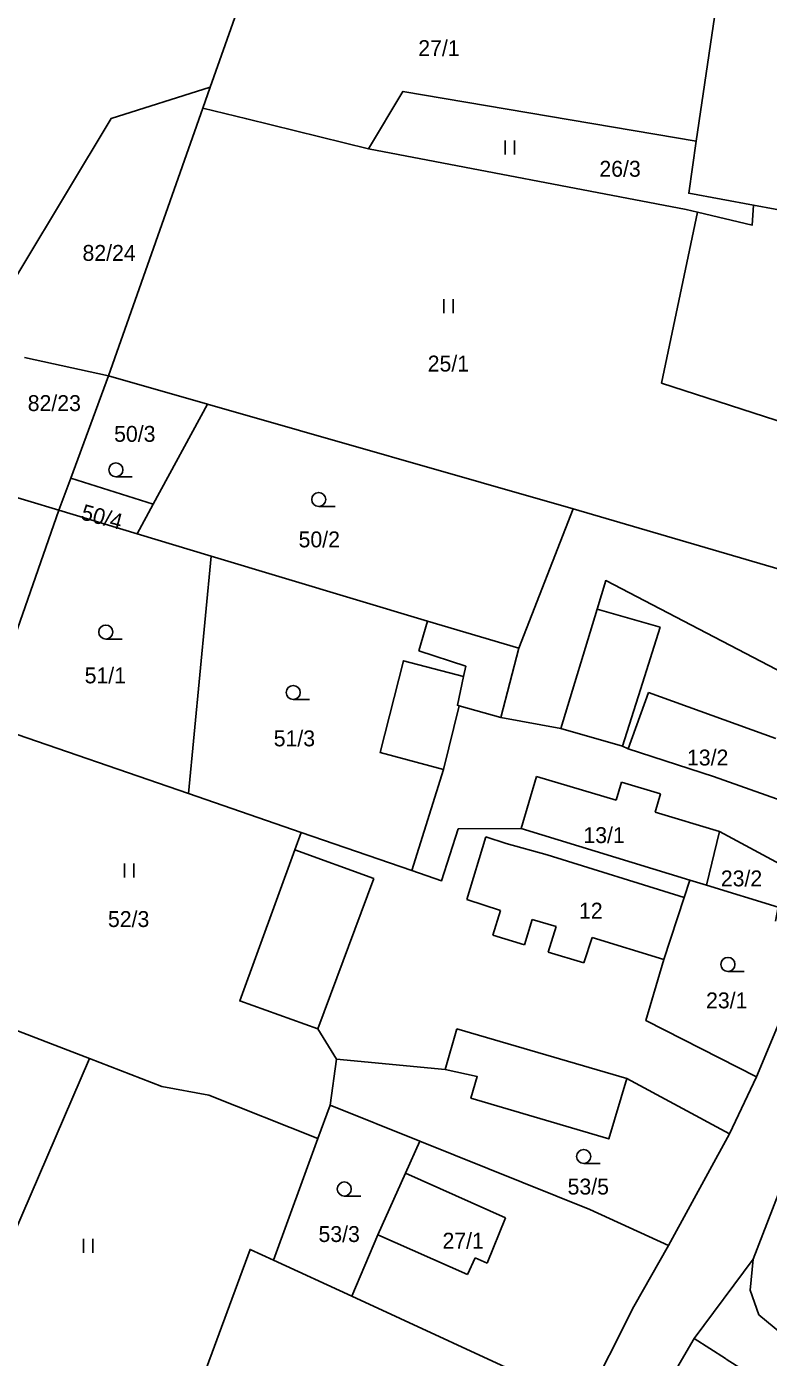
# Model space of a CAD drawing. Extents: x -746176 to -739709, y -1128407 to -1124482.
# Drawn here: x -743036.1 to -742956.8, y -1127574.6 to -1127432.2 of the extents above; entities that cross this region are included whole.
import ezdxf

# ---------------------------------------------------------------- set-up
doc = ezdxf.new("R2010")
doc.units = 0
for name, color, linetype in [('Hranice parcel', 7, 'Continuous'), ('Parcelní čísla', 7, 'Continuous'), ('Vnitřní kresba', 7, 'Continuous'), ('Značky kultur', 7, 'Continuous')]:
    doc.layers.add(name, color=color, linetype=linetype)

msp = doc.modelspace()

# ---------------------------------------------------------------- linework, layer by layer
at = {"layer": 'Hranice parcel'}
for p, q in [((-743016.5, -1127438.72), (-743010.06, -1127420.45)), ((-742962.06, -1127427.67), (-742964.54, -1127444.49)), ((-743017.29, -1127440.95), (-743016.5, -1127438.72)), ((-743017.29, -1127440.95), (-743027.39, -1127469.59)), ((-742968.23, -1127470.39), (-742964.4, -1127452.09)), ((-743027.39, -1127469.59), (-743036.38, -1127467.62)), ((-743027.39, -1127469.59), (-743031.43, -1127480.55)), ((-743027.39, -1127469.59), (-743016.81, -1127472.62)), ((-742947.25, -1127477.16), (-742968.23, -1127470.39)), ((-743016.81, -1127472.62), (-743022.6, -1127483.32)), ((-743016.81, -1127472.62), (-742977.71, -1127483.81)), ((-743031.43, -1127480.55), (-743032.69, -1127483.96)), ((-743031.43, -1127480.55), (-743022.6, -1127483.32)), ((-743032.69, -1127483.96), (-743040.81, -1127481.55)), ((-743032.69, -1127483.96), (-743040.66, -1127506.77)), ((-743024.31, -1127486.49), (-743032.69, -1127483.96)), ((-743022.6, -1127483.32), (-743024.31, -1127486.49)), ((-742977.71, -1127483.81), (-742983.49, -1127498.74)), ((-742954.21, -1127490.71), (-742977.71, -1127483.81)), ((-743024.31, -1127486.49), (-743016.42, -1127488.87)), ((-743018.83, -1127514.29), (-743016.42, -1127488.87)), ((-742983.49, -1127498.74), (-742985.43, -1127506.13)), ((-743040.66, -1127506.77), (-743018.83, -1127514.29)), ((-742979.03, -1127507.34), (-742985.43, -1127506.13)), ((-743018.83, -1127514.29), (-743006.77, -1127518.44)), ((-742983.25, -1127518.03), (-742989.99, -1127518.04)), ((-742965.23, -1127523.55), (-742983.25, -1127518.03)), ((-742994.94, -1127522.52), (-743006.77, -1127518.44)), ((-742965.23, -1127523.55), (-742963.44, -1127524.1)), ((-742958.07, -1127544.59), (-742952.01, -1127529.96)), ((-743029.41, -1127542.64), (-743050.32, -1127534.62)), ((-743029.41, -1127542.64), (-743044.5, -1127577.53)), ((-743003.69, -1127547.61), (-743002.99, -1127542.69)), ((-742960.97, -1127550.69), (-742958.07, -1127544.59)), ((-743005.01, -1127551.2), (-743003.69, -1127547.61)), ((-742994.1, -1127551.47), (-743003.69, -1127547.61)), ((-742960.97, -1127550.69), (-742967.51, -1127562.65)), ((-743009.74, -1127564.2), (-743005.01, -1127551.2)), ((-743001.38, -1127568.05), (-743009.74, -1127564.2)), ((-742964.75, -1127572.6), (-742958.43, -1127564.08)), ((-742979.47, -1127578.16), (-743001.38, -1127568.05))]:
    msp.add_line(p, q, dxfattribs=at)
for points in [[(-743041.59, -1127466.09), (-743027.12, -1127442.06), (-743016.5, -1127438.72)], [(-742964.54, -1127444.49), (-742995.91, -1127439.17), (-742999.6, -1127445.32)], [(-742999.6, -1127445.32), (-743012.61, -1127442.11), (-743017.29, -1127440.95)], [(-742964.4, -1127452.09), (-742965.61, -1127451.81), (-742999.6, -1127445.32)], [(-742964.54, -1127444.49), (-742965.34, -1127450.06), (-742958.39, -1127451.34)], [(-742958.39, -1127451.34), (-742958.54, -1127453.46), (-742964.4, -1127452.09)], [(-742958.39, -1127451.34), (-742942.2, -1127454.33), (-742938.29, -1127453.29), (-742933.5, -1127454.97), (-742931.72, -1127454.21), (-742928.29, -1127455.5)], [(-743016.42, -1127488.87), (-742993.26, -1127495.85), (-742983.49, -1127498.74)], [(-742979.03, -1127507.34), (-742975.14, -1127494.55), (-742974.21, -1127491.49), (-742943.52, -1127507.49)], [(-742985.43, -1127506.13), (-742989.89, -1127504.88), (-742990.08, -1127504.83), (-742989.41, -1127501.75), (-742995.84, -1127500.07), (-742998.35, -1127509.89), (-742991.56, -1127511.71), (-742994.94, -1127522.52)], [(-742947.48, -1127518.45), (-742949.22, -1127517.23), (-742962.69, -1127512.44), (-742971.81, -1127509.49), (-742972.41, -1127509.22), (-742979.03, -1127507.34)], [(-742989.99, -1127518.04), (-742991.77, -1127523.61), (-742994.94, -1127522.52)], [(-742963.44, -1127524.1), (-742962.06, -1127518.33), (-742949.93, -1127524.86)], [(-743006.77, -1127518.44), (-743007.45, -1127520.31), (-743013.35, -1127536.47), (-743005, -1127539.46), (-743002.99, -1127542.69)], [(-742958.07, -1127544.59), (-742969.92, -1127538.58), (-742968.01, -1127532.03), (-742965.83, -1127525.39), (-742965.23, -1127523.55)], [(-742956.04, -1127527.94), (-742955.76, -1127526.44), (-742963.44, -1127524.1)], [(-743005.01, -1127551.2), (-743016.66, -1127546.56), (-743021.68, -1127545.63), (-743029.41, -1127542.64)], [(-743002.99, -1127542.69), (-742991.4, -1127543.81), (-742987.95, -1127544.57), (-742988.63, -1127546.87), (-742973.89, -1127551.23), (-742971.94, -1127544.76), (-742960.97, -1127550.69)], [(-742958.43, -1127564.08), (-742954.72, -1127554.49), (-742950.97, -1127547.61)], [(-742994.1, -1127551.47), (-742995.64, -1127554.9), (-742998.58, -1127561.51), (-743001.38, -1127568.05)], [(-742967.51, -1127562.65), (-742975.9, -1127558.78), (-742994.1, -1127551.47)], [(-743009.74, -1127564.2), (-743012.24, -1127563.05), (-743019.38, -1127582.4), (-743017.56, -1127583.41), (-742993.08, -1127596.96), (-742990.26, -1127591.96)], [(-742967.51, -1127562.65), (-742971.19, -1127569.17), (-742976.43, -1127579.56), (-742979.47, -1127578.16)], [(-742927.53, -1127585.44), (-742934.7, -1127582.76), (-742939.64, -1127581.23), (-742943.72, -1127578.66), (-742953.72, -1127573.43), (-742957.84, -1127570.04), (-742958.76, -1127567.42), (-742958.43, -1127564.08)], [(-742964.75, -1127572.6), (-742970.21, -1127581.92), (-742973.05, -1127587.2), (-742974.2, -1127589.77)], [(-742951.01, -1127581.4), (-742957.06, -1127577.5), (-742961.32, -1127574.78), (-742961.39, -1127574.71), (-742964.75, -1127572.6)]]:
    msp.add_lwpolyline(points, dxfattribs=at)
at = {"layer": 'Vnitřní kresba'}
for p, q in [((-742975.14, -1127494.55), (-742968.39, -1127496.47)), ((-742994.2, -1127499.03), (-742993.26, -1127495.85)), ((-742970.5, -1127503.16), (-742968.39, -1127496.47)), ((-742994.2, -1127499.03), (-742989.17, -1127500.66)), ((-742989.41, -1127501.75), (-742989.17, -1127500.66)), ((-742972.41, -1127509.22), (-742970.5, -1127503.16)), ((-742971.81, -1127509.49), (-742969.62, -1127503.47)), ((-742969.62, -1127503.47), (-742956.03, -1127508.38)), ((-742991.56, -1127511.71), (-742989.89, -1127504.88)), ((-742983.25, -1127518.03), (-742981.6, -1127512.47)), ((-742981.6, -1127512.47), (-742973.1, -1127514.99)), ((-742973.1, -1127514.99), (-742972.53, -1127513.06)), ((-742972.53, -1127513.06), (-742968.35, -1127514.3)), ((-742968.94, -1127516.27), (-742968.35, -1127514.3)), ((-742968.94, -1127516.27), (-742962.06, -1127518.33)), ((-742989.07, -1127525.61), (-742987.02, -1127518.91)), ((-742987.02, -1127518.91), (-742984.85, -1127519.61)), ((-742984.85, -1127519.61), (-742980.49, -1127520.84)), ((-743007.45, -1127520.31), (-742999.03, -1127523.38)), ((-742980.49, -1127520.84), (-742965.83, -1127525.39)), ((-743005, -1127539.46), (-742999.03, -1127523.38)), ((-742989.07, -1127525.61), (-742985.46, -1127526.79)), ((-742986.28, -1127529.44), (-742985.46, -1127526.79)), ((-742982.9, -1127530.47), (-742982.08, -1127527.77)), ((-742982.08, -1127527.77), (-742979.51, -1127528.51)), ((-742986.28, -1127529.44), (-742982.9, -1127530.47)), ((-742980.35, -1127531.26), (-742979.51, -1127528.51)), ((-742976.56, -1127532.4), (-742975.66, -1127529.7)), ((-742975.66, -1127529.7), (-742968.01, -1127532.03)), ((-742980.35, -1127531.26), (-742976.56, -1127532.4)), ((-742991.4, -1127543.81), (-742990.15, -1127539.46)), ((-742990.15, -1127539.46), (-742971.94, -1127544.76)), ((-742995.64, -1127554.9), (-742984.94, -1127559.69)), ((-742986.89, -1127564.52), (-742984.94, -1127559.69)), ((-742998.58, -1127561.51), (-742988.98, -1127565.74)), ((-742988.98, -1127565.74), (-742988.19, -1127563.94)), ((-742988.19, -1127563.94), (-742986.89, -1127564.52))]:
    msp.add_line(p, q, dxfattribs=at)
at = {"layer": 'Značky kultur'}
for p, q in [((-742984.96, -1127445.9), (-742984.96, -1127444.4)), ((-742983.96, -1127445.9), (-742983.96, -1127444.4)), ((-742991.52, -1127462.88), (-742991.52, -1127461.38)), ((-742990.52, -1127462.88), (-742990.52, -1127461.38)), ((-743026.6, -1127480.4), (-743024.85, -1127480.4)), ((-743004.91, -1127483.57), (-743003.16, -1127483.57)), ((-743027.68, -1127497.75), (-743025.93, -1127497.75)), ((-743007.63, -1127504.22), (-743005.88, -1127504.22)), ((-743025.68, -1127523.28), (-743025.68, -1127521.78)), ((-743024.68, -1127523.28), (-743024.68, -1127521.78)), ((-742961.14, -1127533.31), (-742959.39, -1127533.31)), ((-742976.57, -1127553.86), (-742974.82, -1127553.86)), ((-743002.17, -1127557.34), (-743000.42, -1127557.34)), ((-743030.07, -1127563.43), (-743030.07, -1127561.93)), ((-743029.07, -1127563.43), (-743029.07, -1127561.93))]:
    msp.add_line(p, q, dxfattribs=at)
for centre in [(-743026.6, -1127479.65), (-743004.91, -1127482.82), (-743027.68, -1127497), (-743007.63, -1127503.47), (-742961.14, -1127532.56), (-742976.57, -1127553.11), (-743002.17, -1127556.59)]:
    msp.add_circle(centre, 0.75, dxfattribs=at)

# ---------------------------------------------------------------- texts
at = {"layer": 'Parcelní čísla'}
for s, p in [('27/1', (-742994.26, -1127435.38)), ('26/3', (-742974.89, -1127448.29)), ('82/24', (-743030.17, -1127457.29)), ('25/1', (-742993.25, -1127469.13)), ('82/23', (-743036.03, -1127473.36)), ('50/3', (-743026.79, -1127476.65)), ('50/2', (-743007.06, -1127487.94)), ('51/1', (-743029.94, -1127502.49)), ('51/3', (-743009.72, -1127509.23)), ('13/2', (-742965.52, -1127511.28)), ('13/1', (-742976.6, -1127519.58)), ('23/2', (-742961.9, -1127524.21)), ('52/3', (-743027.45, -1127528.56)), ('12', (-742977.07, -1127527.66)), ('23/1', (-742963.48, -1127537.26)), ('53/5', (-742978.29, -1127557.18)), ('53/3', (-743004.93, -1127562.26)), ('27/1', (-742991.67, -1127562.97))]:
    msp.add_text(s, height=1.7, dxfattribs=at).set_placement(p)
msp.add_text('50/4', height=1.7, rotation=345, dxfattribs=at).set_placement((-743030.44, -1127484.93))

doc.saveas('drawing.dxf')
